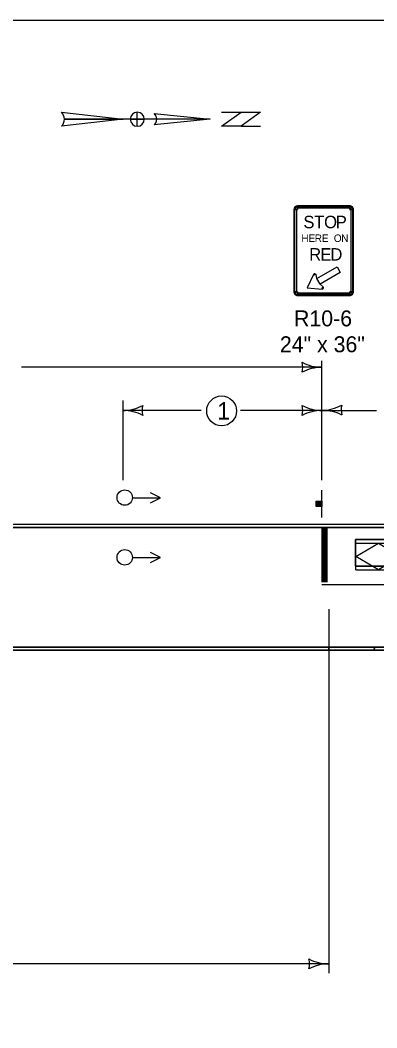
# Model space of a CAD drawing. Extents: x -2134934 to -2127057, y -2139046 to -2137036.
# Drawn here: x -2128115 to -2127757, y -2138047 to -2137036 of the extents above; entities that cross this region are included whole.
import ezdxf

# ---------------------------------------------------------------- set-up
doc = ezdxf.new("R2010")
doc.units = 0
for name, color, linetype in [('Barrier', 7, 'Continuous'), ('BridgeSuperStructureExisting', 7, 'Continuous'), ('Default', 7, 'Continuous'), ('dsnCellsScaleBlock', 7, 'Continuous'), ('DsnShtPlotIdentification', 7, 'Continuous'), ('DsnShtPlotShape', 7, 'Continuous'), ('dsnTextFinalPlan', 7, 'Continuous')]:
    doc.layers.add(name, color=color, linetype=linetype)

msp = doc.modelspace()

# ---------------------------------------------------------------- linework, layer by layer
at = {"layer": 'Barrier'}
for p, q in [((-2127840.1, -2137226.1), (-2127836.4, -2137226.1)), ((-2127839.2, -2137226.1), (-2127837.6, -2137226.1)), ((-2127836.4, -2137226.1), (-2127836.4, -2137222.3)), ((-2127836.4, -2137224.8), (-2127836.4, -2137223.3)), ((-2127783.9, -2137222.3), (-2127783.9, -2137226.1)), ((-2127783.9, -2137223.3), (-2127783.9, -2137224.8)), ((-2127783.9, -2137226.1), (-2127780.1, -2137226.1)), ((-2127782.6, -2137226.1), (-2127781.1, -2137226.1)), ((-2127820.3, -2137291.1), (-2127819.2, -2137291.7)), ((-2127819.2, -2137291.7), (-2127817.9, -2137291.4)), ((-2127836.4, -2137308.6), (-2127840.1, -2137308.6)), ((-2127837.6, -2137308.6), (-2127839.2, -2137308.6)), ((-2127836.4, -2137312.3), (-2127836.4, -2137308.6)), ((-2127836.4, -2137311.4), (-2127836.4, -2137309.8)), ((-2127810.8, -2137303.7), (-2127811.7, -2137304.6)), ((-2127811.7, -2137304.6), (-2127811.7, -2137305.9)), ((-2127780.1, -2137308.6), (-2127783.9, -2137308.6)), ((-2127783.9, -2137308.6), (-2127783.9, -2137312.3)), ((-2127783.9, -2137309.8), (-2127783.9, -2137311.4)), ((-2127781.1, -2137308.6), (-2127782.6, -2137308.6))]:
    msp.add_line(p, q, dxfattribs=at)
for points in [[(-2127836.4, -2137312.3), (-2127783.9, -2137312.3), (-2127783.9, -2137308.6), (-2127780.1, -2137308.6), (-2127780.1, -2137226.1), (-2127783.9, -2137226.1), (-2127783.9, -2137222.3), (-2127836.4, -2137222.3), (-2127836.4, -2137226.1), (-2127840.1, -2137226.1), (-2127840.1, -2137308.6), (-2127836.4, -2137308.6), (-2127836.4, -2137312.3)], [(-2127837.6, -2137226.1), (-2127837.6, -2137308.6), (-2127839.2, -2137308.6), (-2127839.2, -2137226.1), (-2127837.6, -2137226.1)], [(-2127783.9, -2137224.8), (-2127836.4, -2137224.8), (-2127836.4, -2137223.3), (-2127783.9, -2137223.3), (-2127783.9, -2137224.8)], [(-2127782.6, -2137308.6), (-2127782.6, -2137226.1), (-2127781.1, -2137226.1), (-2127781.1, -2137308.6), (-2127782.6, -2137308.6)], [(-2127826.8, -2137304.7), (-2127811.7, -2137305.9), (-2127811.7, -2137304.6), (-2127810.8, -2137303.7), (-2127813.8, -2137301), (-2127817.1, -2137295.3), (-2127817.9, -2137291.4), (-2127819.2, -2137291.7), (-2127820.3, -2137291.1), (-2127826.8, -2137304.7)], [(-2127796.7, -2137283.6), (-2127793.5, -2137289.3), (-2127813.8, -2137301), (-2127817.1, -2137295.3), (-2127796.7, -2137283.6)], [(-2127836.4, -2137309.8), (-2127783.9, -2137309.8), (-2127783.9, -2137311.4), (-2127836.4, -2137311.4), (-2127836.4, -2137309.8)]]:
    msp.add_lwpolyline(points, close=True, dxfattribs=at)
for centre, radius, start, end in [((-2127836.4, -2137226.1), 3.75, 90.0002, 179.9998), ((-2127836.4, -2137226.1), 2.81, 90.0002, 179.9998), ((-2127836.4, -2137226.1), 1.25, 90.0002, 179.9998), ((-2127783.9, -2137226.1), 3.75, 0, 90.0002), ((-2127783.9, -2137226.1), 2.81, 0, 90.0002), ((-2127783.9, -2137226.1), 1.25, 0, 90.0002), ((-2127819.2, -2137291.7), 1.25, 12.6223, 152.2756), ((-2127836.4, -2137308.6), 3.75, 179.9998, 270.0001), ((-2127836.4, -2137308.6), 2.81, 179.9998, 270.0001), ((-2127836.4, -2137308.6), 1.25, 179.9998, 270.0001), ((-2127811.7, -2137304.6), 1.25, 267.7243, 47.3776), ((-2127783.9, -2137308.6), 3.75, 270.0001, 0.0003), ((-2127783.9, -2137308.6), 2.81, 270.0001, 0.0003), ((-2127783.9, -2137308.6), 1.25, 270.0001, 0.0003)]:
    msp.add_arc(centre, radius, start, end, dxfattribs=at)
at = {"layer": 'BridgeSuperStructureExisting'}
for p, q in [((-2127812, -2137497.7), (-2127812, -2137377.9)), ((-2127812, -2137384.3), (-2128113.7, -2137384.3)), ((-2128011.9, -2137417.7), (-2128011.9, -2137497.7)), ((-2127933.2, -2137427.7), (-2128011.9, -2137427.7)), ((-2127811.9, -2137427.7), (-2127893.7, -2137427.7)), ((-2127812, -2137427.7), (-2127757.2, -2137427.7)), ((-2128002.4, -2137515.5), (-2127974.4, -2137515.5)), ((-2127812, -2137535.2), (-2127812, -2137507.7)), ((-2127817.3, -2137524.3), (-2127817.3, -2137518.7)), ((-2127817, -2137518.7), (-2127817, -2137524.3)), ((-2127816.7, -2137524.3), (-2127816.7, -2137518.7)), ((-2127816.4, -2137518.7), (-2127816.4, -2137524.3)), ((-2127816.2, -2137524.3), (-2127816.2, -2137518.7)), ((-2127815.8, -2137518.7), (-2127815.8, -2137524.3)), ((-2127815.6, -2137524.3), (-2127815.6, -2137518.7)), ((-2127815.1, -2137518.7), (-2127815.1, -2137524.3)), ((-2127814.7, -2137524.3), (-2127814.7, -2137518.7)), ((-2127814.4, -2137518.7), (-2127814.4, -2137524.3)), ((-2127814.2, -2137524.3), (-2127814.2, -2137518.7)), ((-2127813.9, -2137518.7), (-2127813.9, -2137524.3)), ((-2127813.6, -2137524.3), (-2127813.6, -2137518.7)), ((-2127813.4, -2137518.7), (-2127813.4, -2137524.3)), ((-2127813.2, -2137524.3), (-2127813.2, -2137518.7)), ((-2127812.9, -2137518.7), (-2127812.9, -2137524.3)), ((-2127812.6, -2137524.3), (-2127812.6, -2137518.7)), ((-2127812.4, -2137518.7), (-2127812.4, -2137524.3)), ((-2127160.1, -2137545.2), (-2128660.1, -2137545.2)), ((-2127812, -2137545.2), (-2127812, -2137600.2)), ((-2127811, -2137545.2), (-2127811, -2137600.2)), ((-2127810, -2137545.2), (-2127810, -2137600.2)), ((-2127809, -2137545.2), (-2127809, -2137600.2)), ((-2127808, -2137545.2), (-2127808, -2137600.2)), ((-2127807, -2137545.2), (-2127807, -2137600.2)), ((-2127778.1, -2137557.2), (-2127733.1, -2137557.2)), ((-2127778.1, -2137584.2), (-2127778.1, -2137557.2)), ((-2127733.1, -2137557.2), (-2127778.1, -2137557.2)), ((-2127778.1, -2137557.2), (-2127778.1, -2137584.2)), ((-2127777.8, -2137587.8), (-2127777.8, -2137560.8)), ((-2127777.8, -2137560.8), (-2127732.8, -2137560.8)), ((-2128002.4, -2137575.5), (-2127974.4, -2137575.5)), ((-2127733.1, -2137584.2), (-2127778.1, -2137584.2)), ((-2127778.1, -2137584.2), (-2127733.1, -2137584.2)), ((-2127777.8, -2137587.8), (-2127732.8, -2137587.8)), ((-2127805.1, -2137627.1), (-2127805.1, -2137992.6)), ((-2128470.1, -2137665.2), (-2127160.1, -2137665.2)), ((-2127805.1, -2137983.3), (-2128464.5, -2137983.3))]:
    msp.add_line(p, q, dxfattribs=at)
for points in [[(-2127984.1, -2137520.3), (-2127974.1, -2137515.3), (-2127984.1, -2137510.3)], [(-2127984.1, -2137580.3), (-2127974.1, -2137575.3), (-2127984.1, -2137570.3)]]:
    msp.add_lwpolyline(points, dxfattribs=at)
msp.add_lwpolyline([(-2127812, -2137518.7), (-2127812, -2137524.3), (-2127817.7, -2137524.3), (-2127817.7, -2137518.7)], close=True, dxfattribs=at)
for centre, radius in [((-2127912.8, -2137428.2), 15), ((-2128010.1, -2137515.2), 7.74), ((-2128010.1, -2137575.2), 7.74)]:
    msp.add_circle(centre, radius, dxfattribs=at)
for centre, radius, start, end in [((-2128011.9, -2137385.2), 42.5, 270, 298.0725), ((-2127976.3, -2137427.7), 16.4, 162.2666, 197.7334), ((-2127847.6, -2137427.7), 16.4, 342.2666, 17.7334), ((-2127811.9, -2137385.2), 42.5, 241.9275, 270), ((-2127812.7, -2137385.2), 42.5, 271.0176, 299.0725), ((-2127776.3, -2137427), 16.4, 163.2666, 198.7334), ((-2128011.9, -2137470.2), 42.5, 61.9275, 90), ((-2127811.9, -2137470.2), 42.5, 90, 118.0725), ((-2127811.2, -2137470.2), 42.5, 62.9275, 90.9824)]:
    msp.add_arc(centre, radius, start, end, dxfattribs=at)
at = {"layer": 'Default'}
msp.add_lwpolyline([(-2130232, -2137035.9), (-2127097, -2137035.9), (-2127097, -2139045.9), (-2130232, -2139045.9)], close=True, dxfattribs=at)
at = {"layer": 'dsnCellsScaleBlock'}
for p, q in [((-2128073.6, -2137128.4), (-2128011.6, -2137135.4)), ((-2127980.6, -2137129.8), (-2127980.6, -2137129.8)), ((-2127980.1, -2137130), (-2127978.9, -2137131.1)), ((-2127924.3, -2137135.4), (-2128070.8, -2137135.4)), ((-2128004.6, -2137135.4), (-2128004.6, -2137135.4)), ((-2127924.3, -2137135.4), (-2127980.6, -2137141.1))]:
    msp.add_line(p, q, dxfattribs=at)
for points in [[(-2128004.6, -2137135.4), (-2127997.5, -2137135.4), (-2127997.5, -2137128.4)], [(-2127980.6, -2137129.8), (-2127924.3, -2137135.4), (-2127977.8, -2137135.4)], [(-2127913, -2137128.4), (-2127873.6, -2137128.4), (-2127893.3, -2137142.5), (-2127873.6, -2137142.5)], [(-2128070.8, -2137135.4), (-2128011.6, -2137135.4), (-2128073.6, -2137142.5)], [(-2127997.5, -2137142.5), (-2127997.5, -2137135.4), (-2127990.5, -2137135.4)]]:
    msp.add_lwpolyline(points, dxfattribs=at)
msp.add_lwpolyline([(-2127913, -2137142.5), (-2127893.3, -2137128.4), (-2127873.6, -2137128.4), (-2127893.3, -2137142.5)], close=True, dxfattribs=at)
for centre, radius, start, end in [((-2128081, -2137135.4), 10.2, 359.9894, 43.619), ((-2127997.5, -2137135.4), 7.04, 90, 180), ((-2127997.5, -2137135.4), 7.04, 360, 90), ((-2127984.9, -2137135.4), 7.04, 0.0204, 53.1257), ((-2128081, -2137135.4), 10.2, 316.4021, 0.0006), ((-2127997.5, -2137135.4), 7.04, 180, 270), ((-2127997.5, -2137135.4), 7.04, 270, 360), ((-2127984.9, -2137135.4), 7.04, 306.8481, 0.0218)]:
    msp.add_arc(centre, radius, start, end, dxfattribs=at)
at = {"layer": 'DsnShtPlotIdentification'}
for p, q in [((-2127160.1, -2137542.2), (-2128660.1, -2137542.2)), ((-2127160.1, -2137542.2), (-2128660.1, -2137542.2)), ((-2127160.1, -2137545.2), (-2128660.1, -2137545.2)), ((-2128660.1, -2137545.2), (-2127810.1, -2137545.2)), ((-2127808.1, -2137545.2), (-2127807.1, -2137545.2)), ((-2127807.1, -2137545.2), (-2127806.1, -2137545.2)), ((-2127806.1, -2137545.2), (-2127805.1, -2137545.2)), ((-2127805.1, -2137545.2), (-2127160.1, -2137545.2)), ((-2127159.5, -2137602.7), (-2127812, -2137602.7)), ((-2128660.1, -2137665.2), (-2127159.5, -2137665.2)), ((-2127805.1, -2137665.2), (-2128280.3, -2137665.2)), ((-2127805.1, -2137668.2), (-2127805.1, -2137665.2)), ((-2127805.1, -2137665.2), (-2127805.1, -2137668.2)), ((-2127758.7, -2137665.2), (-2127805.1, -2137665.2)), ((-2127759.9, -2137668.2), (-2127758.7, -2137665.2)), ((-2127758.7, -2137665.2), (-2127759.9, -2137668.2)), ((-2127160.1, -2137665.2), (-2127758.7, -2137665.2)), ((-2128278.1, -2137668.2), (-2127805.1, -2137668.2)), ((-2127805.1, -2137668.2), (-2127759.9, -2137668.2)), ((-2127759.9, -2137668.2), (-2127160.1, -2137668.2))]:
    msp.add_line(p, q, dxfattribs=at)
for points in [[(-2128471.3, -2137545.2), (-2127158.8, -2137545.2)], [(-2127810.1, -2137545.2), (-2127809.1, -2137545.2), (-2127808.1, -2137545.2)], [(-2127160.1, -2137665.2), (-2128470.1, -2137665.2)], [(-2127160.1, -2137668.2), (-2128470.1, -2137668.2)]]:
    msp.add_lwpolyline(points, dxfattribs=at)
at = {"layer": 'DsnShtPlotShape'}
for centre, radius, start, end in [((-2127847.6, -2137384.4), 16.4, 342.2666, 17.7334), ((-2127812, -2137341.9), 42.5, 241.9275, 270), ((-2127812, -2137426.9), 42.5, 90, 118.0725), ((-2127840.8, -2137983.3), 16.4, 342.2666, 17.7334), ((-2127805.1, -2137940.8), 42.5, 241.9275, 270), ((-2127805.1, -2138025.8), 42.5, 90, 118.0725)]:
    msp.add_arc(centre, radius, start, end, dxfattribs=at)
at = {"layer": 'dsnTextFinalPlan'}
msp.add_lwpolyline([(-2127777.8, -2137574.3), (-2127755.3, -2137560.8), (-2127732.8, -2137574.3), (-2127755.3, -2137587.8)], close=True, dxfattribs=at)

# ---------------------------------------------------------------- texts
at = {"layer": 'Barrier'}
for s, height, p in [('S', 12.5, (-2127830.6, -2137244.8)), ('T', 12.5, (-2127819.8, -2137244.8)), ('O', 12.5, (-2127809.8, -2137244.8)), ('P', 12.5, (-2127798.1, -2137244.8)), ('H', 7.5, (-2127832.6, -2137258.6)), ('E', 7.5, (-2127825.5, -2137258.6)), ('R', 7.5, (-2127819.2, -2137258.6)), ('E', 7.5, (-2127812.1, -2137258.6)), ('O', 7.5, (-2127800, -2137258.6)), ('N', 7.5, (-2127792.6, -2137258.6)), ('R', 12.5, (-2127824.8, -2137277.3)), ('E', 12.5, (-2127813.5, -2137277.3)), ('D', 12.5, (-2127803.5, -2137277.3)), ('R10-6', 16, (-2127840, -2137343.3)), ('24" x 36"', 16, (-2127854.2, -2137369.3))]:
    msp.add_text(s, height=height, dxfattribs=at).set_placement(p)
at = {"layer": 'BridgeSuperStructureExisting'}
msp.add_text('1', height=17.5, dxfattribs=at).set_placement((-2127917.2, -2137436.9))

doc.saveas('drawing.dxf')
